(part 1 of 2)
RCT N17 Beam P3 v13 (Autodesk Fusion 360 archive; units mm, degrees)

design "RCT N17 Beam P3" references "Beam Lock P2 L", "Beam Lock P2 Singlet", "Beam Lock P2 TEE"
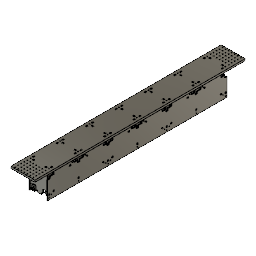
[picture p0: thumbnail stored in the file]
parameter "t_sheet_MAIN" = 6.4 comment "thickness of *most* of the gantry material"
parameter "t_sheet_SECOND" = 3.1 comment "thickness of the webs"
parameter "od_bearings" = 16
parameter "id_bearings" = 5
parameter "t_bearings" = 5
parameter "p_belt" = 2
parameter "w_belt" = 10
parameter "t_belt" = 1.4
parameter "l_top_belt_to_rail" = 3
parameter "r_cutoutTool" = 2.05 (= "4.1 mm / 2")
parameter "hw_m3_thru" = 3.5
parameter "hw_m3_head" = 5.5
parameter "hw_m3_washer" = 7
parameter "hw_m3_thread" = 2.5
parameter "tab_breather" = 0.2 comment "tab clearance"
parameter "hw_m5_thread" = 4.2
parameter "hw_m5_head" = 8.5
parameter "hw_m5_washer" = 10
parameter "hw_m5_thru" = 5.25
parameter "hw_m6_thru" = 6.5
parameter "hw_m6_head" = 10
parameter "hw_m6_washer" = 12
parameter "l_beltblock" = 15
parameter "hw_plstf6_thread" = 2.94
parameter "hw_plstf6_thru" = 4
parameter "hw_plstf6_head" = 6.86
parameter "hw_plstf6_washer" = 7.92
parameter "hw_m3_flathead" = 6
parameter "hw_m4insert_d" = 6
parameter "hw_m4insert_l" = 4.8
parameter "hw_m4_tappedwj" = 3.3
parameter "hw_m4_thru" = 4.25
parameter "hw_m4_head" = 7
parameter "hw_m4_headheight" = 4
parameter "preload_bearings" = 0.55
parameter "hw_m3insert_d" = 5.4
parameter "hw_m3insert_l" = 3.8
parameter "dist_clearance" = 0.5
parameter "hw_shoulder_headDiameter" = 9
parameter "hw_shoulder_headHeight" = 4
parameter "l_travel" = 610 comment "will be rounded to 10s"
parameter "User Parameter" = 0 (= "min 9, odds only pls ... 8 renders to 9 ? mistakes were made")
parameter "l_actual_complete" = 700 (= "round(l_travel / 10) * 10 + ( ( nh_gantry_length * 10 ) * 1 mm )")
parameter "nh_rail_width" = "nh_gantry_width - 3"
parameter "l_shoulder_thread" = 10
parameter "hw_n6_thru" = 4.064
parameter "hw_n6_thread" = 3.1
parameter "hw_n6_flathead" = 6.6548
parameter "hw_n6_head" = 6.858
parameter "carriage_offsets" = 0.25
parameter "hw_momentPin_reald" = 3.683
parameter "deg_gt2z" = 23.244 (= "( ( 360 / ( 2 * ( d1013 + d1014 ) / mm * PI / 2 ) ) * 1 deg )")
parameter "d_beam" = 90
parameter "ptab_width" = 5
parameter "ptab_distback" = 7
parameter "ptab_depth" = 10
parameter "ptab_distadjacent" = 7
parameter "ptab_hole" = 3.25
parameter "ptrelief_width" = 1
parameter "ptrelief_depth" = 1.25
parameter "ptab_rounding" = 2
parameter "ptab_aside" = 3.5
parameter "d344" = 3.5
parameter "d482" = 3.2 (= "t_sheet_MAIN / 2")
parameter "d578" = 0.5
parameter "d683" = 3.683 (= "hw_momentPin_reald")
parameter "d689" = 0.5
parameter "d698" = 5
parameter "d701" = 1.7
parameter "d705" = 3.5415 (= "d683 / 2 + 1.7 mm")
parameter "d837" = 0.25
parameter "d1013" = 4
parameter "d1014" = 0.93 (= "1.38 mm - 0.75 mm + 0.3 mm")
sketch "Basics" plane through (0, 0, 0) normal (0, 1, 0) x axis (1, 0, 0)
  line L1 (40, 0) -> (-0.275, 0)
  line L2 (40, 6.4) -> (40, 0)
  line L3 (-0.275, 6.4) -> (40, 6.4)
  line L4 (-0.275, 0) -> (-0.275, 6.4)
  line L5 (1.7678, -1.7678) -> (-1.7678, 1.7678)
  line L6 (-9.5459, -13.0815) -> (1.7678, -1.7678)
  line L7 (-13.0815, -9.5459) -> (-9.5459, -13.0815)
  line L8 (-1.7678, 1.7678) -> (-13.0815, -9.5459)
  line L9 (1.7678, 8.1678) -> (-1.7678, 4.6322)
  line L10 (-9.5459, 19.4815) -> (1.7678, 8.1678)
  line L11 (-13.0815, 15.9459) -> (-9.5459, 19.4815)
  line L12 (-1.7678, 4.6322) -> (-13.0815, 15.9459)
  line L13 (-14.4957, 3.182) -> (-7.4246, -3.8891)
  line L14 (-14.4957, 3.218) -> (-7.4246, 10.2891)
  line L15 (40, -7.9505) -> (-15, -7.9505)
  line L16 (40, -14.3505) -> (40, -7.9505)
  line L17 (-15, -14.3505) -> (40, -14.3505)
  line L18 (-15, -7.9505) -> (-15, -14.3505)
  line L19 (-3.8891, -13.7886) -> (-7.0711, -10.6066)
  line L20 (-0.7071, -10.6066) -> (-3.8891, -13.7886)
  line L21 (-3.8891, -7.4246) -> (-0.7071, -10.6066)
  line L22 (-1.2926, 3.45) -> (-1.2926, 2.95)
  line L23 (-13.2886, 15.4459) -> (-1.2926, 3.45)
  line L24 (-15, 15.4459) -> (-13.2886, 15.4459)
  line L25 (-15, -7.8505) -> (-15, 15.4459)
  line L26 (-1.2926, 2.95) -> (-12.0931, -7.8505)
  line L27 (-9.564, 3.2) -> (-15, -2.236)
  line L28 (-15, 8.636) -> (-9.564, 3.2)
  line L29 (-13.0108, 4.6669) -> (-14.4957, 3.182)
  line L30 (-5.9397, -2.4042) -> (-13.0108, 4.6669)
  line L31 (5, -14.3505) -> (5, -3.3926)
  line L32 (-10, -14.3505) -> (-10, -7.9505)
  line L33 (0, -14.3505) -> (0, -7.9505)
  line L34 (5, -7.8505) -> (-15, -7.8505)
  line L35 (5, -1.1505) -> (5, -3.3926)
  line L36 (-1.2926, -1.1505) -> (5, -1.1505)
  line L37 (-1.2926, 15.4459) -> (-1.2926, 3.45)
  line L38 (-13.2886, 15.4459) -> (-1.2926, 15.4459)
  line L39 (-15, -7.9505) -> (-15, -7.8505)
  line L40 (95, -7.9505) -> (95, -14.3505)
  line L41 (95, -7.9505) -> (95, -7.8505)
  line L42 (89.5459, -13.0815) -> (78.2322, -1.7678)
  line L43 (95, -14.3505) -> (40, -14.3505)
  line L44 (75, -7.8505) -> (95, -7.8505)
  line L45 (80.275, 6.4) -> (40, 6.4)
  line L46 (40, 0) -> (80.275, 0)
  line L47 (40, -7.9505) -> (95, -7.9505)
  line L48 (89.5459, 19.4815) -> (78.2322, 8.1678)
  line L49 (80.7071, -10.6066) -> (83.8891, -13.7886)
  line L50 (90, -14.3505) -> (90, -7.9505)
  line L51 (81.2926, 15.4459) -> (81.2926, 3.45)
  line L52 (83.8891, -13.7886) -> (87.0711, -10.6066)
  line L53 (81.2926, 2.95) -> (92.0931, -7.8505)
  line L54 (89.564, 3.2) -> (95, -2.236)
  line L55 (81.7678, 4.6322) -> (93.0815, 15.9459)
  line L56 (81.2926, 3.45) -> (81.2926, 2.95)
  line L57 (93.0815, -9.5459) -> (89.5459, -13.0815)
  line L58 (93.2886, 15.4459) -> (81.2926, 3.45)
  line L59 (93.2886, 15.4459) -> (81.2926, 15.4459)
  line L60 (93.0815, 15.9459) -> (89.5459, 19.4815)
  line L61 (83.8891, -7.4246) -> (80.7071, -10.6066)
  line L62 (95, 8.636) -> (89.564, 3.2)
  line L63 (85.9397, -2.4042) -> (93.0108, 4.6669)
  line L64 (95, 15.4459) -> (93.2886, 15.4459)
  line L65 (93.0108, 4.6669) -> (94.4957, 3.182)
  line L66 (81.7678, 1.7678) -> (93.0815, -9.5459)
  line L67 (75, -1.1505) -> (75, -3.3926)
  line L68 (81.2926, -1.1505) -> (75, -1.1505)
  line L69 (94.4957, 3.182) -> (87.4246, -3.8891)
  line L70 (94.4957, 3.218) -> (87.4246, 10.2891)
  line L71 (80.275, 0) -> (80.275, 6.4)
  line L72 (95, -7.8505) -> (95, 15.4459)
  line L73 (78.2322, 8.1678) -> (81.7678, 4.6322)
  line L74 (78.2322, -1.7678) -> (81.7678, 1.7678)
  line L75 (75, -14.3505) -> (75, -3.3926)
  line L76 (80, -14.3505) -> (80, -7.9505)
  line L77 (-1.2926, -1.1505) -> (-1.2926, 2.95)
  line L78 (81.2926, 2.95) -> (81.2926, -1.1505)
  line L79 (75, -7.4505) -> (95, -7.4505)
  line L80 (89, -7.4505) -> (89, 15.4459)
  line L81 (95, -1.1505) -> (89, -1.1505)
  line L82 (90, -0.6505) -> (95, -0.6505)
  line L83 (90, 15.4459) -> (90, -0.6505)
  point P1 (0, 0)
  point P14 (-7.4246, -3.8891)
  point P16 (-7.4246, 10.2891)
  point P19 (40, -7.9505)
  point P22 (-7.0711, -10.6066)
  point P25 (-3.8891, -7.4246)
  point P26 (-1.2926, 2.95)
  point P32 (-1.2926, 2.95)
  point P18 (-15, -7.9505)
  point P33 (-15, -2.236)
  point P35 (-15, 8.636)
  point P37 (-5.9397, -2.4042)
  point P39 (5, -14.3505)
  point P40 (-10, -7.9505)
  point P41 (-10, -14.3505)
  point P42 (0, -7.9505)
  point P43 (0, -14.3505)
  point P44 (-15, -7.8505)
  point P45 (5, -7.8505)
  point P31 (-12.0931, -7.8505)
  point P30 (-15, -7.8505)
  point P88 (80, 0)
  point P2 (-0.275, 0)
  point P86 (80.275, 0)
  point P3 (40, 0)
  point P95 (40, 0)
  point P4 (40, 6.4)
  point P94 (40, 6.4)
  point P5 (-0.275, 6.4)
  point P91 (80.275, 6.4)
  point P6 (-1.7678, 1.7678)
  point P87 (81.7678, 1.7678)
  point P7 (1.7678, -1.7678)
  point P90 (78.2322, -1.7678)
  point P8 (-9.5459, -13.0815)
  point P89 (89.5459, -13.0815)
  point P9 (-13.0815, -9.5459)
  point P81 (93.0815, -9.5459)
  point P10 (-1.7678, 4.6322)
  point P72 (81.7678, 4.6322)
  point P11 (1.7678, 8.1678)
  point P82 (78.2322, 8.1678)
  point P12 (-9.5459, 19.4815)
  point P83 (89.5459, 19.4815)
  point P13 (-13.0815, 15.9459)
  point P78 (93.0815, 15.9459)
  point P84 (87.4246, -3.8891)
  point P15 (-14.4957, 3.182)
  point P85 (94.4957, 3.182)
  point P79 (87.4246, 10.2891)
  point P17 (-14.4957, 3.218)
  point P92 (94.4957, 3.218)
  point P53 (95, -7.9505)
  point P96 (40, -7.9505)
  point P20 (40, -14.3505)
  point P93 (40, -14.3505)
  point P21 (-15, -14.3505)
  point P57 (95, -14.3505)
  point P67 (87.0711, -10.6066)
  point P23 (-3.8891, -13.7886)
  point P62 (83.8891, -13.7886)
  point P24 (-0.7071, -10.6066)
  point P65 (80.7071, -10.6066)
  point P59 (83.8891, -7.4246)
  point P61 (81.2926, 2.95)
  point P27 (-1.2926, 3.45)
  point P58 (81.2926, 3.45)
  point P28 (-13.2886, 15.4459)
  point P60 (93.2886, 15.4459)
  point P29 (-15, 15.4459)
  point P66 (95, 15.4459)
  point P64 (95, -7.8505)
  point P63 (92.0931, -7.8505)
  point P68 (81.2926, 2.95)
  point P52 (95, -2.236)
  point P34 (-9.564, 3.2)
  point P49 (89.564, 3.2)
  point P51 (95, 8.636)
  point P36 (-13.0108, 4.6669)
  point P54 (93.0108, 4.6669)
  point P56 (85.9397, -2.4042)
  point P38 (5, -3.3926)
  point P50 (75, -3.3926)
  point P55 (75, -14.3505)
  point P80 (90, -7.9505)
  point P77 (90, -14.3505)
  point P76 (80, -7.9505)
  point P73 (80, -14.3505)
  point P75 (95, -7.8505)
  point P71 (75, -7.8505)
  point P46 (5, -1.1505)
  point P74 (75, -1.1505)
  point P47 (-1.2926, -1.1505)
  point P70 (81.2926, -1.1505)
  point P48 (-1.2926, 15.4459)
  point P69 (81.2926, 15.4459)
  point P97 (-1.2926, -1.1505)
  point P98 (95, -7.4505)
  point P99 (75, -7.4505)
  point P100 (89, 15.4459)
  point P101 (89, -7.4505)
  point P102 (89, -1.1505)
  point P103 (95, -1.1505)
  point P104 (95, -0.6505)
  point P106 (90, 15.4459)
  point P107 (0, 6.4)
  horizontal L1
  vertical L2
  horizontal L3
  vertical L4
  perpendicular L5 L6
  parallel L5 L7
  parallel L6 L8
  perpendicular L9 L10
  parallel L9 L11
  parallel L10 L12
  equal L5 L9
  equal L6 L12
  midpoint P1 L5
  midpoint L8 P14
  perpendicular L8 L13
  midpoint L12 P16
  perpendicular L12 L14
  equal L13 L14
  horizontal L15
  vertical L16
  horizontal L17
  vertical L18
  coincident L2 P19
  coincident L6 P22
  perpendicular L6 L19
  perpendicular L19 L20
  coincident L6 P25
  perpendicular L6 L21
  midpoint L6 P25
  vertical L22
  perpendicular L14 L23
  perpendicular L22 L24
  perpendicular L17 L25
  perpendicular L13 L26
  coincident P26 P32
  coincident P18 L25
  coincident L25 P33
  perpendicular L13 L27
  coincident L25 P35
  perpendicular L14 L28
  perpendicular L13 L29
  coincident L8 P37
  perpendicular L8 L30
  coincident L17 P39
  perpendicular L17 L31
  coincident L15 P40
  coincident L17 P41
  perpendicular L17 L32
  coincident L15 P42
  coincident L17 P43
  perpendicular L17 L33
  coincident P1 L33
  coincident L25 P44
  coincident L31 P45
  perpendicular L31 L34
  coincident P31 L34
  coincident P30 L34
  vertical L35
  perpendicular L35 L36
  parallel L22 L37
  perpendicular L22 L38
  symmetric P1 L16 P88
  symmetric P2 L16 P86
  symmetric P3 L16 P95
  symmetric P4 L16 P94
  symmetric P5 L16 P91
  symmetric P6 L16 P87
  symmetric P7 L16 P90
  symmetric P8 L16 P89
  symmetric P9 L16 P81
  symmetric P10 L16 P72
  symmetric P11 L16 P82
  symmetric P12 L16 P83
  symmetric P13 L16 P78
  symmetric P14 L16 P84
  symmetric P15 L16 P85
  symmetric P16 L16 P79
  symmetric P17 L16 P92
  symmetric P18 L16 P53
  symmetric P19 L16 P96
  symmetric P20 L16 P93
  symmetric P21 L16 P57
  symmetric L16 P22 P67
  symmetric L16 P23 P62
  symmetric L16 P24 P65
  symmetric L16 P25 P59
  symmetric L16 P26 P61
  symmetric L16 P27 P58
  symmetric L16 P28 P60
  symmetric L16 P29 P66
  symmetric L16 P30 P64
  symmetric L16 P31 P63
  symmetric L16 P32 P68
  symmetric L16 P33 P52
  symmetric L16 P34 P49
  symmetric L16 P35 P51
  symmetric L16 P36 P54
  symmetric L16 P37 P56
  symmetric L16 P38 P50
  symmetric L16 P39 P55
  symmetric L16 P40 P80
  symmetric L16 P41 P77
  symmetric L16 P42 P76
  symmetric L16 P43 P73
  symmetric L16 P44 P75
  symmetric L16 P45 P71
  symmetric L16 P46 P74
  symmetric L16 P47 P70
  symmetric L16 P48 P69
  parallel L22 L77
  coincident P47 P97
  coincident L72 P98
  coincident L75 P99
  perpendicular L75 L79
  coincident L59 P100
  coincident L79 P101
  perpendicular L79 L80
  coincident L80 P102
  coincident L72 P103
  perpendicular L72 L81
  coincident P70 L81
  coincident L72 P104
  perpendicular L80 L82
  coincident L59 P106
  perpendicular L59 L83
  coincident P1 L1
  midpoint L9 P107
  vertical P1 P107
  coincident L3 P107
  dimension "d560" distance P2 P5 = 6.4 (= "t_sheet_MAIN")
  dimension "d563" distance P8 P9 = 5 (= "t_bearings")
  dimension "d564" distance P7 P8 = 16 (= "od_bearings")
  dimension "d565" angle L3 L12 = 45 (= "d566")
  dimension "d566" angle L1 L8 = 45
  dimension "d567" distance P16 P17 = 10 (= "l_shoulder_thread")
  dimension "d568" distance P19 P20 = 6.4 (= "t_sheet_MAIN")
  dimension "d569" distance P20 P21 = 55 (= "( ( nh_gantry_width * 10 ) * 1 mm + 10 mm ) / 2")
  dimension "d571" distance P24 P25 = 4.5 (= "hw_shoulder_headHeight + 0.5 mm")
  dimension "d572" distance P23 P24 = 4.5 (= "hw_shoulder_headDiameter / 2")
  dimension "d574" = 8.8037
  dimension "d576" distance L8 L26 = 0.5
  dimension "d577" distance L12 L23 = 0.5
  dimension "d580" distance P13 L24 = 0.5
  dimension "d581" distance L13 P34 = 3.5 (= "hw_m4insert_d / 2 + 0.5 mm")
  dimension "d582" distance L14 P34 = 3.5 (= "d581")
  dimension "d583" distance P15 P36 = 2.1
  dimension "d584" = 0.8383
  dimension "d586" distance P8 L17 = 1.269 (= "0.5 mm + 0.769 mm")
  dimension "d587" distance L18 L32 = 5
  dimension "d588" distance L32 L33 = 10
  dimension "d589" distance L31 L33 = 5
  dimension "d623" distance L15 L34 = 0.1
  dimension "d624" = 1.6455
  dimension "d625" = 3.4128
  dimension "d626" distance P39 P46 = 13.2 (= "0.5 in + 0.5 mm")
  dimension "d696" distance P26 P27 = 0.5
  dimension "d708" distance P53 L79 = 0.5
  dimension "d739" distance L72 L80 = 6
  dimension "d747" distance L81 L82 = 0.5
  dimension "d748" distance L80 L83 = 1
  dimension "d801" distance P1 L4 = 0.275 (= "preload_bearings / 2")
  dimension "d1521" OffsetX = 0
  dimension "d1522" OffsetY = 0
  dimension "d1523" OffsetZ = 0
  dimension "d1524" AngleZ = 0
  dimension "d1576" OffsetX = 0
  dimension "d1577" OffsetY = 0
  dimension "d1578" OffsetZ = 0
  dimension "d1579" AngleZ = 0
extrude "Extrude56" new body sketch "Basics" profile of L1 L2 L3 L4 L45 L46 L71 along normal blind 700 (= "l_actual_complete") bodies "Rail"
sketch "Planar Guides" plane through (0, 0, 0) normal (0, 0, 1) x axis (-1, 0, 0)
  line L1 (-80.275, 0) -> (0.275, 0)
  line L2 (-80.275, -700) -> (-80.275, 0)
  line L3 (0.275, -700) -> (-80.275, -700)
  line L4 (0.275, 0) -> (0.275, -700)
  line L5 (-80.275, -55) -> (0.275, -55)
  line L6 (0.275, -58.1) -> (-80.275, -58.1)
  line L7 (0.275, -350) -> (-80.275, -350)
  line L8 (-8.45, -350) -> (-8.45, 0)
  line L9 (-11.55, -350) -> (-11.55, 0)
  line L10 (-40, -350) -> (-40, 0)
  line L11 (-80.275, -152.8167) -> (0.275, -152.8167)
  line L12 (-80.275, -155.9167) -> (0.275, -155.9167)
  line L13 (-80.275, -51) -> (0.275, -51)
  line L14 (-4.45, -350) -> (-4.45, 0)
  line L15 (-80.275, -348.45) -> (0.275, -348.45)
  line L16 (-80.275, -47) -> (0.275, -47)
  line L17 (-80.275, -159.9167) -> (0.275, -159.9167)
  line L18 (-80.275, -163.9167) -> (0.275, -163.9167)
  line L19 (-11.55, -63.55) -> (-8.45, -63.55)
  line L20 (-11.55, -68.55) -> (-8.45, -68.55)
  line L21 (-10, -68.55) -> (-10, -63.55)
  line L22 (-17, -58.1) -> (-17, -55)
  line L23 (-22, -58.1) -> (-22, -55)
  line L24 (-22, -56.55) -> (-17, -56.55)
  line L25 (-11.55, -105.4583) -> (-8.45, -105.4583)
  line L26 (-16, -58.1) -> (-16, -55)
  line L27 (-23, -58.1) -> (-23, -55)
  line L28 (-11.55, -62.55) -> (-8.45, -62.55)
  line L29 (-11.55, -69.55) -> (-8.45, -69.55)
  line L30 (-80.275, -155.9167) -> (-80.275, -152.8167)
  line L31 (-11.55, -60.05) -> (-8.45, -60.05)
  line L32 (-13.5, -55) -> (-13.5, -58.1)
  line L33 (-11.55, -72.55) -> (-8.45, -72.55)
  line L34 (-26, -55) -> (-26, -58.1)
  circle C1 centre (-40, -5) radius 1.65
  circle C2 centre (-10, -5) radius 1.65
  circle C3 centre (-10, -45) radius 1.65
  circle C4 centre (-10, -56.55) radius 1.625
  point P7 (-40, 0)
  point P6 (-40, -5)
  point P8 (-10, -5)
  point P9 (-10, -45)
  point P14 (-80.275, -350)
  point P15 (0.275, -350)
  point P10 (0.275, -55)
  point P13 (0.275, -58.1)
  point P11 (-80.275, -55)
  point P12 (-80.275, -58.1)
  point P16 (-8.45, 0)
  point P17 (-8.45, -350)
  point P18 (-11.55, 0)
  point P19 (-11.55, -350)
  point P20 (-40, 0)
  point P21 (-40, -350)
  point P22 (0.275, -152.8167)
  point P23 (-80.275, -152.8167)
  point P24 (0.275, -155.9167)
  point P25 (-80.275, -155.9167)
  point P26 (0.275, -51)
  point P27 (-80.275, -51)
  point P28 (-4.45, 0)
  point P29 (-4.45, -350)
  point P30 (0.275, -348.45)
  point P31 (-80.275, -348.45)
  point P32 (0.275, -47)
  point P33 (-80.275, -47)
  point P34 (0.275, -159.9167)
  point P35 (-80.275, -159.9167)
  point P36 (0.275, -163.9167)
  point P37 (-80.275, -163.9167)
  point P38 (-8.45, -63.55)
  point P39 (-11.55, -63.55)
  point P40 (-8.45, -68.55)
  point P41 (-11.55, -68.55)
  point P42 (-10, -63.55)
  point P43 (-10, -68.55)
  point P44 (-17, -55)
  point P45 (-17, -58.1)
  point P46 (-22, -55)
  point P47 (-22, -58.1)
  point P48 (-17, -56.55)
  point P49 (-22, -56.55)
  point P50 (-8.45, -105.4583)
  point P51 (-11.55, -105.4583)
  point P52 (-16, -55)
  point P53 (-16, -58.1)
  point P54 (-23, -55)
  point P55 (-23, -58.1)
  point P56 (-8.45, -62.55)
  point P57 (-11.55, -62.55)
  point P58 (-8.45, -69.55)
  point P59 (-11.55, -69.55)
  point P60 (-80.275, -154.3667)
  point P61 (-10, -56.55)
  point P62 (-8.45, -60.05)
  point P63 (-11.55, -60.05)
  point P64 (-13.5, -58.1)
  point P65 (-13.5, -55)
  point P66 (-8.45, -72.55)
  point P67 (-11.55, -72.55)
  point P68 (-26, -58.1)
  point P69 (-26, -55)
  midpoint L1 P7
  vertical P6 P7
  horizontal P6 P8
  equal C1 C2
  vertical P8 P9
  equal C1 C3
  horizontal L5
  horizontal L6
  midpoint L2 P14
  midpoint L4 P15
  coincident L4 P10
  coincident L4 P13
  coincident L2 P11
  coincident L2 P12
  coincident L1 P16
  coincident L7 P17
  perpendicular L7 L8
  coincident L1 P18
  coincident L7 P19
  perpendicular L7 L9
  coincident P7 P20
  midpoint L7 P21
  coincident L4 P22
  coincident L2 P23
  perpendicular L2 L11
  coincident L4 P24
  coincident L2 P25
  perpendicular L2 L12
  coincident L4 P26
  coincident L2 P27
  perpendicular L2 L13
  coincident L1 P28
  coincident L7 P29
  perpendicular L7 L14
  coincident L4 P30
  coincident L2 P31
  perpendicular L2 L15
  coincident L4 P32
  coincident L2 P33
  perpendicular L2 L16
  coincident L4 P34
  coincident L2 P35
  perpendicular L2 L17
  coincident L4 P36
  coincident L2 P37
  perpendicular L2 L18
  coincident L8 P38
  coincident L9 P39
  perpendicular L8 L19
  coincident L8 P40
  coincident L9 P41
  perpendicular L9 L20
  midpoint L19 P42
  midpoint L20 P43
  coincident L5 P44
  coincident L6 P45
  perpendicular L6 L22
  coincident L5 P46
  coincident L6 P47
  perpendicular L6 L23
  midpoint L22 P48
  midpoint L23 P49
  equal L21 L24
  coincident L8 P50
  coincident L9 P51
  perpendicular L9 L25
  coincident L5 P52
  coincident L6 P53
  perpendicular L6 L26
  coincident L5 P54
  coincident L6 P55
  perpendicular L6 L27
  coincident L8 P56
  coincident L9 P57
  perpendicular L8 L28
  coincident L8 P58
  coincident L9 P59
  perpendicular L9 L29
  midpoint L30 P60
  coincident L21 P61
  coincident L24 P61
  coincident L8 P62
  coincident L9 P63
  perpendicular L9 L31
  coincident L6 P64
  coincident L5 P65
  perpendicular L5 L32
  coincident L8 P66
  coincident L9 P67
  perpendicular L9 L33
  coincident L6 P68
  coincident L5 P69
  perpendicular L5 L34
  dimension "d1152" diameter C1 = 3.3 (= "hw_m4_tappedwj")
  dimension "d1153" distance P6 P7 = 5
  dimension "d1154" distance P6 P8 = 30 (= "( nh_gantry_width / 2 - 2 ) * 10 mm")
  dimension "d1162" distance P8 P9 = 40 (= "( ( nh_ears - 1 ) * 10 ) * 1 mm")
  dimension "d1164" distance P10 P13 = 3.1 (= "t_sheet_SECOND")
  dimension "d1165" distance P9 L5 = 10
  dimension "d1166" distance P9 L8 = 1.55 (= "d1164 / 2")
  dimension "d1167" distance P9 L9 = 1.55 (= "d1166")
  dimension "d1168" distance L11 L12 = 3.1 (= "d1164")
  dimension "d1169" distance L5 L11 = 97.8167 (= "l_beamunits")
  dimension "d1170" distance L5 L13 = 4
  dimension "d1171" distance L8 L14 = 4 (= "d1170")
  dimension "d1174" distance L7 L15 = 1.55 (= "t_sheet_SECOND / 2")
  dimension "d1175" = 102
  dimension "d1181" distance L13 L16 = 4
  dimension "d1182" distance L12 L17 = 4 (= "d1170")
  dimension "d1183" distance L17 L18 = 4 (= "d1170")
  dimension "d1414" distance P42 P43 = 5 (= "ptab_width")
  dimension "d1427" distance P49 L25 = 48.9083 (= "l_beamunits / 2")
  dimension "d1428" distance L19 L28 = 1 (= "ptrelief_width")
  dimension "d1431" distance L20 L29 = 1 (= "d1428")
  dimension "d1432" distance L22 L26 = 1 (= "d1428")
  dimension "d1433" distance L23 L27 = 1 (= "d1428")
  dimension "d1549" diameter C4 = 3.25 (= "ptab_hole")
  dimension "d1550" distance L22 P61 = 7 (= "ptab_distadjacent")
  dimension "d1551" distance P42 P61 = 7 (= "ptab_distadjacent")
  dimension "d1554" distance P61 L32 = 3.5 (= "ptab_aside")
  dimension "d1555" distance P61 L31 = 3.5 (= "d1554")
  dimension "d1568" distance L23 L34 = 4 (= "ptab_rounding * 2")
  dimension "d1569" distance L20 L33 = 4 (= "d1568")
work_plane "WorkPlane2"
work_plane "WorkPlane6" AlongDistance 36.55
work_plane "WorkPlane7" AlongDistance 30
work_plane "WorkPlane8" AlongDistance 88.663
work_plane "WorkPlane9" AlongDistance 140.775
extrude "Extrude125" cut sketch "Planar Guides" profile of C2 to an object
rectangular_pattern "R-Pattern3" countU 7 (= "nh_gantry_width - 3") uSpaceDistance 10 vSpaceDistance 10
mirror "Mirror8"
extrude "Extrude126" cut sketch "Planar Guides" profile of L5 L6 L9 L10 blind -79.6 (= "-d_beam + t_sheet_MAIN + 4 mm")
extrude "Extrude127" cut sketch "Planar Guides" profile of L5 L6 L8 L9 L19 L20 L25 L28 L29 C4 L31 no distance stored bodies "Top Web"
extrude "Extrude170" cut sketch "Planar Guides" profile of L5 L6 L8 L9 L19 L20 L22 L23 C4 no distance stored
mirror "Mirror49"
mirror "Mirror50"
rectangular_pattern "R-Pattern9" uSpaceDistance 97.8167 (= "l_beamunits") vSpaceDistance 0
extrude "Extrude171" cut sketch "Planar Guides" profile of L5 L6 L8 L9 L19 L20 L22 L23 L26 L27 L28 L29 C4 L31 L32 L33 L34 no distance stored
extrude "Extrude172" cut sketch "Planar Guides" profile of L5 L6 L8 L9 C4 L31 L32 against normal blind 30
extrude "Extrude173" cut sketch "Planar Guides" profile of L5 L6 L8 L9 L19 L20 L22 L23 L26 L27 L28 L29 no distance stored
extrude "Extrude174" cut sketch "Planar Guides" profile of L5 L6 L8 L9 L19 L20 L22 L23 blind -4
fillet "Fillet132" radius 2 (= "ptab_rounding")
fillet "Fillet133" radius 0.5 (= "ptrelief_width / 2")
fillet "Fillet134" radius 1
extrude "Extrude175" new body sketch "Planar Guides" profile of L5 L6 L8 L9 L19 L20 L22 L23 no distance stored from offset -0.5
combine "Combine44"
combine "Combine45"
sketch "Sketch47" plane through (8.45, 0, 0) normal (-1, 0, 0) x axis (0, -1, 0)
  line L1 (-68.55, -7.15) -> (-68.55, -0.5)
  line L2 (-69.55, -6.4) -> (-69.55, -7.15)
  line L3 (-105.4583, -6.4) -> (-69.55, -6.4)
  line L4 (-105.4583, -90) -> (-105.4583, -6.4)
  line L5 (-55, -90) -> (-105.4583, -90)
  line L6 (-55, -30) -> (-55, -90)
  line L7 (-59.05, -30) -> (-55, -30)
  line L8 (-60.05, -24.4) -> (-60.05, -29)
  line L9 (-71.55, -23.4) -> (-61.05, -23.4)
  line L10 (-72.55, -15.4) -> (-72.55, -22.4)
  line L11 (-65.55, -17.4) -> (-66.55, -17.4)
  line L12 (-60.05, -13.4) -> (-61.55, -13.4)
  line L13 (-60.05, -6.4) -> (-60.05, -13.4)
  line L14 (-62.55, -6.4) -> (-60.05, -6.4)
  line L15 (-62.55, -7.15) -> (-62.55, -6.4)
  line L16 (-63.55, -0.5) -> (-63.55, -7.15)
  line L17 (-68.55, -0.5) -> (-63.55, -0.5)
  line L18 (-58.1, -86) -> (-55, -86)
  line L19 (-51, -90) -> (-55, -90)
  line L20 (-51, -30) -> (-51, -90)
  line L21 (-55, -30) -> (-51, -30)
  line L22 (-58.1, -86) -> (-58.1, -30)
  line L23 (-58.1, -77) -> (-55, -77)
  line L24 (-55, -72) -> (-58.1, -72)
  line L25 (-55, -68) -> (-58.1, -68)
  line L26 (-58.1, -78) -> (-55, -78)
  line L27 (-58.1, -71) -> (-55, -71)
  line L28 (-58.1, -80.5) -> (-55, -80.5)
  arc A1 centre (-69.05, -7.15) radius 0.5 clockwise from (-68.55, -7.15) to (-69.55, -7.15)
  arc A2 centre (-59.05, -29) radius 1 clockwise from (-59.05, -30) to (-60.05, -29)
  arc A3 centre (-61.05, -24.4) radius 1 clockwise from (-61.05, -23.4) to (-60.05, -24.4)
  arc A4 centre (-71.55, -22.4) radius 1 clockwise from (-71.55, -23.4) to (-72.55, -22.4)
  arc A5 centre (-70.55, -15.4) radius 2 clockwise from (-72.55, -15.4) to (-68.55, -15.4)
  arc A6 centre (-66.55, -15.4) radius 2 clockwise from (-66.55, -17.4) to (-68.55, -15.4)
  arc A7 centre (-65.55, -15.4) radius 2 clockwise from (-63.55, -15.4) to (-65.55, -17.4)
  arc A8 centre (-61.55, -15.4) radius 2 clockwise from (-63.55, -15.4) to (-61.55, -13.4)
  arc A9 centre (-63.05, -7.15) radius 0.5 clockwise from (-62.55, -7.15) to (-63.55, -7.15)
  circle C1 centre (-56.55, -84) radius 1.625
  point P9 (-55, -90)
  point P40 (-55, -90)
  point P10 (-55, -30)
  point P43 (-55, -30)
  point P45 (-55, -77)
  point P46 (-58.1, -77)
  point P47 (-58.1, -72)
  point P48 (-55, -72)
  point P49 (-58.1, -68)
  point P50 (-55, -68)
  point P51 (-55, -78)
  point P53 (-55, -71)
  point P54 (-58.1, -71)
  point P52 (-58.1, -78)
  point P55 (-55, -80.5)
  point P56 (-58.1, -80.5)
  point P37 (-56.55, -84)
  point P41 (-51, -90)
  coincident P9 P40
  perpendicular L6 L19
  perpendicular L5 L20
  perpendicular L6 L21
  coincident P10 P43
  coincident L6 P45
  perpendicular L22 L23
  coincident L22 P46
  coincident L22 P47
  coincident L6 P48
  perpendicular L6 L24
  coincident L22 P49
  coincident L6 P50
  horizontal L25
  coincident L6 P51
  perpendicular L22 L26
  coincident L6 P53
  perpendicular L6 L27
  coincident L22 P54
  coincident L22 P52
  coincident L6 P55
  coincident L22 P56
  perpendicular L22 L28
  dimension "d1604" distance L6 P37 = 1.55 (= "t_sheet_SECOND / 2")
  dimension "d1605" diameter C1 = 3.25 (= "ptab_hole")
  dimension "d1606" distance P37 L18 = 2
  dimension "d1607" distance P40 P41 = 4
  dimension "d1608" distance L24 L25 = 4 (= "ptab_rounding * 2")
  dimension "d1609" distance L23 L24 = 5 (= "ptab_width")
  dimension "d1610" distance P37 L23 = 7 (= "ptab_distadjacent")
  dimension "d1611" distance L23 L26 = 1 (= "ptrelief_width")
  dimension "d1612" distance L24 L27 = 1 (= "ptrelief_width")
  dimension "d1615" distance P37 L28 = 3.5 (= "ptab_aside")
extrude "Extrude177" new body sketch "Sketch47" profile of L6 C1 L19 L20 L21 no distance stored
combine "Combine50"
extrude "Extrude178" cut sketch "Sketch47" profile of L6 C1 L22 L23 L24 no distance stored
extrude "Extrude179" cut sketch "Sketch47" profile of L6 L22 L23 L24 L26 L27 along a picked direction no distance stored
extrude "Extrude180" new body sketch "Sketch47" profile of L6 L22 L23 L24 no distance stored from offset -0.5
combine "Combine49"
fillet "Fillet135" radius 0.5 (= "ptrelief_width / 2")
extrude "Extrude181" cut sketch "Sketch47" profile of L6 C1 L18 L22 L28 against normal blind 25
extrude "Extrude182" cut sketch "Sketch47" profile of L6 L22 L23 L24 L25 L26 L27 L28 along a picked direction no distance stored
extrude "Extrude183" cut sketch "Sketch47" profile of L6 L22 L23 L24 along a picked direction blind -4
fillet "Fillet136" radius 2 (= "ptab_rounding")
fillet "Fillet137" radius 1
sketch "Sketch49" plane through (0, 55, 0) normal (0, -1, 0) x axis (1, 0, 0)
  line L1 (22.55, -74) -> (22.55, -75)
  line L2 (27.55, -68) -> (20.55, -68)
  line L3 (28.55, -80.5) -> (28.55, -69)
  line L4 (33.45, -80.5) -> (28.55, -80.5)
  line L5 (40, -6.4) -> (40, -86)
  line L6 (23, -6.4) -> (40, -6.4)
  line L7 (23, -7.15) -> (23, -6.4)
  line L8 (22, -0.5) -> (22, -7.15)
  line L9 (17, -0.5) -> (22, -0.5)
  line L10 (17, -7.15) -> (17, -0.5)
  line L11 (16, -6.4) -> (16, -7.15)
  line L12 (13.5, -6.4) -> (16, -6.4)
  line L13 (13.5, -13.4) -> (13.5, -6.4)
  line L14 (15, -13.4) -> (13.5, -13.4)
  line L15 (20, -17.4) -> (19, -17.4)
  line L16 (26, -22.4) -> (26, -15.4)
  line L17 (14.5, -23.4) -> (25, -23.4)
  line L18 (13.5, -29) -> (13.5, -24.4)
  line L19 (11.55, -30) -> (12.5, -30)
  line L20 (11.55, -71) -> (11.55, -30)
  line L21 (12.3, -71) -> (11.55, -71)
  line L22 (8.95, -72) -> (12.3, -72)
  line L23 (8.95, -77) -> (8.95, -72)
  line L24 (12.3, -77) -> (8.95, -77)
  line L25 (11.55, -78) -> (12.3, -78)
  line L26 (11.55, -80.5) -> (11.55, -78)
  line L27 (18.55, -80.5) -> (11.55, -80.5)
  line L28 (18.55, -79) -> (18.55, -80.5)
  line L29 (34, -17) -> (40, -17)
  line L30 (34, -6.4) -> (34, -17)
  line L31 (80.275, 0) -> (-0.275, 0)
  line L32 (33.45, -86) -> (33.45, -80.5)
  line L33 (40, -86) -> (33.45, -86)
  arc A1 centre (20.55, -75) radius 2 clockwise from (22.55, -75) to (20.55, -77)
  arc A2 centre (20.55, -74) radius 2 clockwise from (20.55, -72) to (22.55, -74)
  arc A3 centre (20.55, -70) radius 2 clockwise from (20.55, -72) to (20.55, -68)
  arc A4 centre (27.55, -69) radius 1 clockwise from (27.55, -68) to (28.55, -69)
  arc A5 centre (22.5, -7.15) radius 0.5 clockwise from (23, -7.15) to (22, -7.15)
  arc A6 centre (16.5, -7.15) radius 0.5 clockwise from (17, -7.15) to (16, -7.15)
  arc A7 centre (15, -15.4) radius 2 clockwise from (15, -13.4) to (17, -15.4)
  arc A8 centre (19, -15.4) radius 2 clockwise from (19, -17.4) to (17, -15.4)
  arc A9 centre (20, -15.4) radius 2 clockwise from (22, -15.4) to (20, -17.4)
  arc A10 centre (24, -15.4) radius 2 clockwise from (22, -15.4) to (26, -15.4)
  arc A11 centre (25, -22.4) radius 1 clockwise from (26, -22.4) to (25, -23.4)
  arc A12 centre (14.5, -24.4) radius 1 clockwise from (13.5, -24.4) to (14.5, -23.4)
  arc A13 centre (12.5, -29) radius 1 clockwise from (13.5, -29) to (12.5, -30)
  arc A14 centre (12.3, -71.5) radius 0.5 clockwise from (12.3, -71) to (12.3, -72)
  arc A15 centre (12.3, -77.5) radius 0.5 clockwise from (12.3, -77) to (12.3, -78)
  arc A16 centre (20.55, -79) radius 2 clockwise from (18.55, -79) to (20.55, -77)
  point P62 (40, -17)
  point P64 (34, -6.4)
  point P63 (34, -17)
  coincident L5 P62
  perpendicular L5 L29
  perpendicular L6 L30
  coincident L6 P64
  dimension "d1765" distance P62 P63 = 6
  dimension "d1766" distance L29 L31 = 17
mirror "Mirror52" bodies "Perp Web (1)"
combine "Combine51" bodies "Perp Web (1)"
rectangular_pattern "R-Pattern11" countU 7 (= "n_beamunits + 1") uSpaceDistance 97.8167 (= "l_beamunits") vSpaceDistance 0 bodies "Perp Web (1)", "Perp Web (2)", "Perp Web (3)", "Perp Web (4)", "Perp Web (5)", "Perp Web (6)"
split "Split9" bodies "Top Web (1)"
mirror "Mirror53" bodies "Top Web (1) (1)"
combine "Combine52" bodies "Top Web (1) (1)"
mirror "Mirror54" bodies "Top Web (2)"
sketch "Sketch48" plane through (8.45, 0, 0) normal (-1, 0, 0) x axis (0, -1, 0)
  line L1 (-56.55, -85.625) -> (-56.55, -90)
  line L2 (-56.55, -77) -> (-56.55, -82.375)
  line L3 (-58.1, -77) -> (-56.55, -77)
  line L4 (-58.1, -72) -> (-58.1, -77)
  line L5 (-56.55, -72) -> (-58.1, -72)
  line L6 (-56.55, -30) -> (-56.55, -72)
  line L7 (-59.05, -30) -> (-56.55, -30)
  line L8 (-60.05, -24.4) -> (-60.05, -29)
  line L9 (-71.55, -23.4) -> (-61.05, -23.4)
  line L10 (-72.55, -15.4) -> (-72.55, -22.4)
  line L11 (-65.55, -17.4) -> (-66.55, -17.4)
  line L12 (-60.05, -13.4) -> (-61.55, -13.4)
  line L13 (-60.05, -6.4) -> (-60.05, -13.4)
  line L14 (-62.55, -6.4) -> (-60.05, -6.4)
  line L15 (-62.55, -7.15) -> (-62.55, -6.4)
  line L16 (-63.55, -0.5) -> (-63.55, -7.15)
  line L17 (-68.55, -0.5) -> (-63.55, -0.5)
  line L18 (-68.55, -7.15) -> (-68.55, -0.5)
  line L19 (-69.55, -6.4) -> (-69.55, -7.15)
  line L20 (-141.3667, -6.4) -> (-69.55, -6.4)
  line L21 (-141.3667, -7.15) -> (-141.3667, -6.4)
  line L22 (-142.3667, -0.5) -> (-142.3667, -7.15)
  line L23 (-147.3667, -0.5) -> (-142.3667, -0.5)
  line L24 (-147.3667, -7.15) -> (-147.3667, -0.5)
  line L25 (-148.3667, -6.4) -> (-148.3667, -7.15)
  line L26 (-150.8667, -6.4) -> (-148.3667, -6.4)
  line L27 (-150.8667, -13.4) -> (-150.8667, -6.4)
  line L28 (-149.3667, -13.4) -> (-150.8667, -13.4)
  line L29 (-144.3667, -17.4) -> (-145.3667, -17.4)
  line L30 (-138.3667, -22.4) -> (-138.3667, -15.4)
  line L31 (-149.8667, -23.4) -> (-139.3667, -23.4)
  line L32 (-150.8667, -29) -> (-150.8667, -24.4)
  line L33 (-154.3667, -30) -> (-151.8667, -30)
  line L34 (-154.3667, -72) -> (-154.3667, -30)
  line L35 (-152.8167, -72) -> (-154.3667, -72)
  line L36 (-152.8167, -77) -> (-152.8167, -72)
  line L37 (-154.3667, -77) -> (-152.8167, -77)
  line L38 (-154.3667, -82.375) -> (-154.3667, -77)
  line L39 (-154.3667, -90) -> (-154.3667, -85.625)
  line L40 (-56.55, -90) -> (-154.3667, -90)
  line L41 (-131.734, -22.522) -> (-67.8634, -76.4727)
  line L42 (-129.7336, -20.1537) -> (-131.734, -22.522)
  line L43 (-65.863, -74.1045) -> (-129.7336, -20.1537)
  line L44 (-67.8634, -76.4727) -> (-65.863, -74.1045)
  line L45 (-66.8632, -75.2886) -> (-56.55, -84)
  line L46 (-144.8667, -9.4) -> (-130.7338, -21.3379)
  line L47 (-147.3667, -6.4) -> (-142.3667, -6.4)
  line L48 (-144.8667, -6.4) -> (-144.8667, -17.4)
  line L49 (-97.7983, -47.1291) -> (-99.7987, -49.4973)
  line L50 (-67.7728, -72.4913) -> (-69.7732, -74.8595)
  line L51 (-68.5368, -71.846) -> (-70.5371, -74.2142)
  line L52 (-72.3564, -68.6195) -> (-74.3568, -70.9877)
  line L53 (-73.1204, -67.9742) -> (-75.1208, -70.3425)
  line L54 (-75.4122, -66.0384) -> (-77.4126, -68.4066)
  line L55 (-127.0598, -22.4123) -> (-129.0602, -24.7805)
  line L56 (-123.2401, -25.6387) -> (-125.2405, -28.0069)
  arc A1 centre (-56.55, -84) radius 1.625 clockwise from (-56.55, -85.625) to (-56.55, -82.375)
  arc A2 centre (-59.05, -29) radius 1 clockwise from (-59.05, -30) to (-60.05, -29)
  arc A3 centre (-61.05, -24.4) radius 1 clockwise from (-61.05, -23.4) to (-60.05, -24.4)
  arc A4 centre (-71.55, -22.4) radius 1 clockwise from (-71.55, -23.4) to (-72.55, -22.4)
  arc A5 centre (-70.55, -15.4) radius 2 clockwise from (-72.55, -15.4) to (-68.55, -15.4)
  arc A6 centre (-66.55, -15.4) radius 2 clockwise from (-66.55, -17.4) to (-68.55, -15.4)
  arc A7 centre (-65.55, -15.4) radius 2 clockwise from (-63.55, -15.4) to (-65.55, -17.4)
  arc A8 centre (-61.55, -15.4) radius 2 clockwise from (-63.55, -15.4) to (-61.55, -13.4)
  arc A9 centre (-63.05, -7.15) radius 0.5 clockwise from (-62.55, -7.15) to (-63.55, -7.15)
  arc A10 centre (-69.05, -7.15) radius 0.5 clockwise from (-68.55, -7.15) to (-69.55, -7.15)
  arc A11 centre (-141.8667, -7.15) radius 0.5 clockwise from (-141.3667, -7.15) to (-142.3667, -7.15)
  arc A12 centre (-147.8667, -7.15) radius 0.5 clockwise from (-147.3667, -7.15) to (-148.3667, -7.15)
  arc A13 centre (-149.3667, -15.4) radius 2 clockwise from (-149.3667, -13.4) to (-147.3667, -15.4)
  arc A14 centre (-145.3667, -15.4) radius 2 clockwise from (-145.3667, -17.4) to (-147.3667, -15.4)
  arc A15 centre (-144.3667, -15.4) radius 2 clockwise from (-142.3667, -15.4) to (-144.3667, -17.4)
  arc A16 centre (-140.3667, -15.4) radius 2 clockwise from (-142.3667, -15.4) to (-138.3667, -15.4)
  arc A17 centre (-139.3667, -22.4) radius 1 clockwise from (-138.3667, -22.4) to (-139.3667, -23.4)
  arc A18 centre (-149.8667, -24.4) radius 1 clockwise from (-150.8667, -24.4) to (-149.8667, -23.4)
  arc A19 centre (-151.8667, -29) radius 1 clockwise from (-150.8667, -29) to (-151.8667, -30)
  arc A20 centre (-154.3667, -84) radius 1.625 clockwise from (-154.3667, -82.375) to (-154.3667, -85.625)
  circle C1 centre (-133.4076, -19.0793) radius 1.625
  circle C2 centre (-64.1894, -77.5471) radius 1.625
  point P5 (-56.55, -84)
  point P86 (-56.55, -84)
  point P87 (-66.8632, -75.2886)
  point P88 (-130.7338, -21.3379)
  point P92 (-144.8667, -17.4)
  point P93 (-144.8667, -6.4)
  point P89 (-144.8667, -9.4)
  point P94 (-133.4076, -19.0793)
  point P95 (-99.7987, -49.4973)
  point P96 (-97.7983, -47.1291)
  point P97 (-64.1894, -77.5471)
  point P98 (-69.7732, -74.8595)
  point P99 (-67.7728, -72.4913)
  point P100 (-70.5371, -74.2142)
  point P101 (-68.5368, -71.846)
  point P102 (-74.3568, -70.9877)
  point P103 (-72.3564, -68.6195)
  point P104 (-75.1208, -70.3425)
  point P105 (-73.1204, -67.9742)
  point P106 (-77.4126, -68.4066)
  point P107 (-75.4122, -66.0384)
  point P109 (-129.0602, -24.7805)
  point P110 (-127.0598, -22.4123)
  point P111 (-125.2405, -28.0069)
  point P112 (-123.2401, -25.6387)
  perpendicular L41 L42
  parallel L41 L43
  parallel L42 L44
  coincident P5 P86
  midpoint L44 P87
  parallel L41 L45
  midpoint L42 P88
  perpendicular L42 L46
  midpoint L29 P92
  midpoint L47 P93
  coincident P89 L48
  coincident L46 P94
  midpoint L41 P95
  midpoint L43 P96
  coincident L45 P97
  coincident L41 P98
  coincident L43 P99
  perpendicular L43 L50
  coincident L41 P100
  coincident L43 P101
  perpendicular L43 L51
  coincident L41 P102
  coincident L43 P103
  perpendicular L43 L52
  coincident L41 P104
  coincident L43 P105
  perpendicular L43 L53
  coincident L41 P106
  coincident L43 P107
  perpendicular L43 L54
  coincident L41 P109
  coincident L43 P110
  perpendicular L43 L55
  coincident L41 P111
  coincident L43 P112
  perpendicular L43 L56
  dimension "d1656" distance L41 L43 = 3.1 (= "t_sheet_SECOND")
  dimension "d1657" distance P89 L47 = 3
  dimension "d1658" distance L42 P94 = 3.5 (= "d1662")
  dimension "d1659" diameter C1 = 3.25 (= "ptab_hole")
  dimension "d1660" distance P89 P94 = 15
  dimension "d1661" diameter C2 = 3.25 (= "ptab_hole")
  dimension "d1662" distance L44 P97 = 3.5 (= "ptab_aside")
  dimension "d1663" distance L52 L53 = 1 (= "ptrelief_width")
  dimension "d1664" distance L50 L51 = 1 (= "d1663")
  dimension "d1665" distance P97 L51 = 7 (= "ptab_distadjacent")
  dimension "d1667" distance L51 L52 = 5 (= "ptab_width")
  dimension "d1668" distance L52 L54 = 4 (= "ptab_rounding * 2")
  dimension "d1689" distance L55 L56 = 5 (= "ptab_width")
  dimension "d1690" distance P94 L55 = 7 (= "ptab_distadjacent")
  dimension "d1767" distance P86 P97 = 10
extrude "Extrude184" cut sketch "Sketch48" profile of L41 L43 C1 C2 L51 L52 L55 L56 no distance stored
extrude "Extrude185" new body sketch "Sketch48" profile of L41 L43 L44 L49 L50 L51 L52 L53 L54 to an object
extrude "Extrude186" cut sketch "Sketch48" profile of L41 L43 L50 L51 L52 L53 along a picked direction no distance stored
fillet "Fillet138" radius 0.5 (= "ptrelief_width / 2")
extrude "Extrude187" new body sketch "Sketch48" profile of L41 L43 L51 L52 no distance stored from offset -0.5
combine "Combine54"
extrude "Extrude188" cut sketch "Sketch48" profile of L41 L43 L44 L50 L51 L52 L53 L54 along a picked direction no distance stored
extrude "Extrude189" cut sketch "Sketch48" profile of L41 L43 L51 L52 along a picked direction blind -4
fillet "Fillet139" radius 2 (= "ptab_rounding")
fillet "Fillet140" radius 1
mirror "Mirror55"
combine "Combine55"
mirror "Mirror56"
combine "Combine56"
mirror "Mirror58" bodies "Top Web (1) (1)"
rectangular_pattern "R-Pattern14" countU 3 (= "n_beamunits / 2") uSpaceDistance 195.6333 (= "l_beamunits * 2") vSpaceDistance 0 bodies "Top Web (1) (2)", "Top Web (1) (1) (1)", "Top Web (1) (3)", "Top Web (1) (1) (2)"
combine "Combine57" bodies "Top Web (1)", "Top Web (1) (1)", "Top Web (1) (2)", "Top Web (1) (1) (1)", "Top Web (2)", "Top Web (1) (3)", "Top Web (1) (1) (2)"
mirror "Mirror59" bodies "Top Web (1)"
component_insert "Component Insert4"
joint "Assemble5" OffsetX 0 OffsetY 0 OffsetZ 0 AngleZ 0 alignAngle -90 alignOffsetX 0 alignOffsetY 0 alignOffsetZ -0.75
component_insert "Component Insert5"
joint "Assemble6" OffsetX 0 OffsetY 0 OffsetZ 0 AngleZ 0 alignAngle 270 alignOffsetX 0 alignOffsetY 0 alignOffsetZ -0.75
component_insert "Component Insert6"
joint "Assemble7" OffsetX 0 OffsetY 0 OffsetZ 0 AngleZ 0 alignAngle 180 alignOffsetX 0 alignOffsetY 0 alignOffsetZ -0.75
component_insert "Component Insert7"
joint "Assemble8" OffsetX 0 OffsetY 0 OffsetZ 0 AngleZ 0 alignAngle 0 alignOffsetX 0 alignOffsetY 0 alignOffsetZ -0.75
joint "Assemble9" OffsetX 0 OffsetY 0 OffsetZ 0 AngleZ 0 alignAngle 0 alignOffsetX 0 alignOffsetY 0 alignOffsetZ 0
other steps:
joint_origin "JointOrigin7" OffsetX 0 OffsetY 0 OffsetZ 0 AngleZ 0
joint_origin "JointOrigin8" OffsetX 0 OffsetY 0 OffsetZ 0 AngleZ 0
joint_origin "JointOrigin9" OffsetX 0 OffsetY 0 OffsetZ 0 AngleZ 0
joint_origin "JointOrigin10" OffsetX 0 OffsetY 0 OffsetZ 0 AngleZ 0
joint_origin "JointOrigin11" OffsetX 0 OffsetY 0 OffsetZ 0 AngleZ 0
named bodies: "Rail", "Perp Web", "Top Web", "Perp Web (1)", "Perp Web (2)", "Perp Web (3)", "Perp Web (4)", "Top Web (1)", "Top Web (1) (1)", "Top Web (2)", "Top Web (1) (2)", "Top Web (1) (1) (1)", "Perp Web (5)", "Perp Web (6)", "Top Web (1) (3)", "Top Web (1) (1) (2)"

design "Beam Lock P2 L"
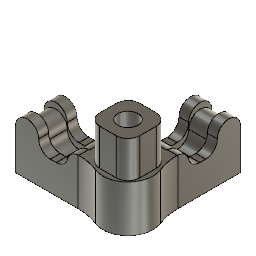
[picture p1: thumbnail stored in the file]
parameter "heatset_entry" = 5.2
parameter "heatset_depth" = 4
parameter "heatset_taperby" = 0.2
parameter "recip_thickness" = 3.2
parameter "recip_slotwidth" = 7
parameter "print_wall" = 0.435 (= "( 0.87 / 2 ) * 1 mm")
parameter "recip_distfrom" = 4.5
parameter "recip_tooth" = 1 comment "extra length to lock-in"
parameter "recip_slotdepth" = 10
sketch "Sketch1" plane through (0, 0, 0) normal (0, 0, 1) x axis (1, 0, 0)
  line L1 (-16, -1.6) -> (-12, -1.6)
  line L2 (-16, 1.6) -> (-16, -1.6)
  line L3 (-12, 1.6) -> (-16, 1.6)
  line L4 (-12, -1.6) -> (-12, 1.6)
  line L5 (0, 1.73) -> (0, 2.6)
  line L6 (0, -1.73) -> (0, -2.6)
  line L7 (0, 4.3) -> (0, 2.6)
  line L8 (0, -4.3) -> (0, -2.6)
  line L9 (-7, 1.6) -> (-12, 1.6)
  line L10 (-7, -1.6) -> (-12, -1.6)
  line L11 (-7, -1.6) -> (-7, 1.6)
  line L12 (-4, 1.6) -> (-7, 1.6)
  line L13 (-4, -1.6) -> (-4, 1.6)
  line L14 (-7, -1.6) -> (-4, -1.6)
  line L15 (-4, 3.3) -> (-4, 1.6)
  line L16 (-16, 3.3) -> (-4, 3.3)
  line L17 (-16, 1.6) -> (-16, 3.3)
  line L18 (-16, 0) -> (0, 0)
  line L19 (-12, 3.3) -> (-12, 1.6)
  line L20 (-7, 3.3) -> (-7, 1.6)
  line L21 (-2.7568, 3.3) -> (-4, 3.3)
  line L22 (3.43, -3.43) -> (-3.43, -3.43)
  line L23 (3.43, 3.43) -> (3.43, -3.43)
  line L24 (-3.43, 3.43) -> (3.43, 3.43)
  line L25 (-3.43, -3.43) -> (-3.43, 3.43)
  line L26 (3.43, 3.43) -> (-3.43, -3.43)
  line L27 (-3.43, 3.43) -> (3.43, -3.43)
  circle C1 centre (0, 0) radius 1.625
  circle C2 centre (0, 0) radius 3
  circle C3 centre (0, 0) radius 2.6
  circle C4 centre (0, 0) radius 1.73
  circle C5 centre (0, 0) radius 4.3
  point P1 (0, 0)
  point P2 (0, 0)
  point P5 (0, 0)
  point P10 (0, 2.6)
  point P11 (0, -2.6)
  point P12 (0, 1.73)
  point P13 (0, -1.73)
  point P14 (-12, 0)
  point P3 (0, 0)
  point P4 (0, 0)
  point P15 (0, 0)
  point P16 (0, 4.3)
  point P17 (0, -4.3)
  point P18 (-7, -1.6)
  point P21 (-7, -1.6)
  point P8 (-16, 1.6)
  point P24 (-16, 1.6)
  point P25 (0, 0)
  point P26 (-16, 0)
  point P27 (-12, 3.3)
  point P28 (-7, 3.3)
  point P30 (-2.7568, 3.3)
  point P35 (0, 0)
  point P36 (0, -3.43)
  point P37 (0, -1.73)
  point P7 (-16, -1.6)
  point P9 (-12, 1.6)
  point P20 (-4, -1.6)
  point P23 (-16, 3.3)
  coincident P1 P2
  concentric C1 C2
  concentric C2 C3
  coincident P1 P5
  horizontal L1
  vertical L2
  horizontal L3
  coincident C3 P10
  coincident C3 P11
  coincident C4 P12
  coincident C4 P13
  vertical L4
  midpoint L4 P14
  coincident P3 L5
  coincident P4 L6
  vertical L5
  vertical L6
  horizontal P1 P14
  coincident P1 P15
  coincident C5 P16
  vertical L7
  coincident C5 P17
  parallel L7 L8
  perpendicular L4 L9
  perpendicular L4 L10
  perpendicular L11 L12
  perpendicular L12 L13
  perpendicular L13 L14
  coincident P18 P21
  perpendicular L12 L15
  perpendicular L15 L16
  perpendicular L16 L17
  coincident P8 P24
  coincident P2 P25
  midpoint L2 P26
  coincident L16 P27
  perpendicular L16 L19
  coincident L16 P28
  perpendicular L16 L20
  vertical L20
  coincident C5 P30
  perpendicular L15 L21
  perpendicular L22 L23
  parallel L22 L24
  parallel L23 L25
  horizontal L22
  coincident L26 P35
  coincident L27 P35
  coincident P5 P35
  midpoint L22 P36
  coincident P13 P37
  equal L22 L25
  dimension "d1" diameter C1 = 3.25
  dimension "d2" diameter C2 = 6
  dimension "d3" diameter C3 = 5.2 (= "heatset_entry")
  dimension "d4" distance C3 C4 = 0.87 (= "print_wall * 2")
  dimension "d11" distance P7 P8 = 3.2 (= "recip_thickness")
  dimension "d29" distance P8 P9 = 4
  dimension "d69" distance P11 P17 = 1.7
  dimension "d70" distance L4 P18 = 5
  dimension "d71" distance P20 P21 = 3
  dimension "d72" distance P23 P24 = 1.7
  dimension "d95" distance P15 L13 = 4
  dimension "d99" distance P36 P37 = 1.7
  dimension "d104" distance P15 L22 = 3.43
extrude "Extrude7" new body sketch "Sketch1" profile of C3 C4 L2 L3 L4 L5 L6 C5 L7 L8 L9 L11 L12 L13 L14 L15 L16 L17 L18 L19 L20 L21 along normal blind 8 (= "heatset_depth + 4 mm")
extrude "Extrude9" cut sketch "Sketch1" profile of C3 C4 L5 L6 L18 along normal blind 4 (= "heatset_depth")
chamfer "Chamfer8" distance 0.2 (= "heatset_taperby") distance 4 (= "heatset_depth")
chamfer "Chamfer9" distance 0.4
extrude "Extrude8" sketch "Sketch1" profile of L4 C5 L9 L11 L16 L18 L19 L20 blind -4
extrude "Extrude10" sketch "Sketch1" profile of L9 L16 L19 L20 blind 1
extrude "Extrude11" sketch "Sketch1" profile of L3 L16 L17 L19 blind 1
fillet "Fillet12" radius 2
fillet "Fillet13" radius 2
fillet "Fillet14" radius 10
mirror "Mirror2"
combine "Combine2"
chamfer "Chamfer10" distance 0.87
copy_paste_bodies "CopyPasteBodies2"
move "Move2"
combine "Combine4"
fillet "Fillet16" radius 4
extrude "Extrude12" sketch "Sketch1" profile of C3 C4 L5 L6 C5 L7 L8 L18 L21 L22 L23 L24 L25 blind 6.25
fillet "Fillet17" radius 2
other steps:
base_feature "Base Feature"

design "Beam Lock P2 TEE"
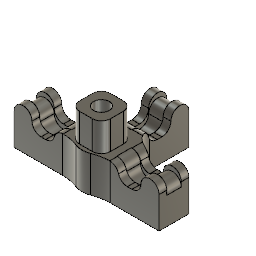
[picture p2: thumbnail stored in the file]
parameter "heatset_entry" = 5.2
parameter "heatset_depth" = 4
parameter "heatset_taperby" = 0.2
parameter "recip_thickness" = 3.2
parameter "recip_slotwidth" = 7
parameter "print_wall" = 0.435 (= "( 0.87 / 2 ) * 1 mm")
parameter "recip_distfrom" = 4.5
parameter "recip_tooth" = 1 comment "extra length to lock-in"
parameter "recip_slotdepth" = 10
